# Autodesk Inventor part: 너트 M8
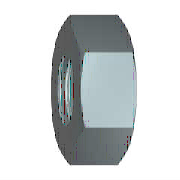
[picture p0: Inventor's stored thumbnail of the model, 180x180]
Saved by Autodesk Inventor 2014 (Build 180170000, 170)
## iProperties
IsCustomPart: 1
Created: 2012-02
Part Number: 너트 M8
Material: 강철, 연강
Description: 6각 너트 및 6각 가는 너트
Document SubType Name: Modeling
Standard: KS B 1012
Designer: mduedu
Standards Organization: KS
Language: ko-KR
Size Designation: M 8
Categories: <MemberInstance><Categories><Category DisplayName="조임쇠" InternalName="e4da775c-781d-43d5-af7c-5136215cf5a6" Mnemonic="FSTN"><Category DisplayName="너트" InternalN
Density: 1 g/cm^3
Appearance: 강철
Author: mduedu
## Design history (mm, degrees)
sketch "스케치1"
  geometry: L1 (-7.506, 0)-(-3.753, 6.5); L2 (-3.753, 6.5)-(3.753, 6.5); L3 (3.753, 6.5)-(7.506, 0); L4 (7.506, 0)-(3.753, -6.5); L5 (3.753, -6.5)-(-3.753, -6.5); L6 (-3.753, -6.5)-(-7.506, 0); 2 further points
  constraints: 12 end point, 1 coincident, 1 horizontal, 11 other
  dimensions: "d0" = 15.01111 distance of L3.end L1.start (= 1.1547 x SW)
extrude "본체" new body sketch "스케치1" distance "d1" = 5 (= KOH); taper "d2" = 0 deg
sketch "스케치2"
  geometry: L1 (0, 3.753)-(0, 7.506) reference; L2 (0, 7.506)-(5, 7.506) reference; L3 (5, 3.753)-(5, 7.506) reference; L4 (-1, 0)-(6, 0) reference; L5 (0.581, 7.506)-(0, 6.5); L6 (4.419, 7.506)-(5, 6.5)
  constraints: 4 end point, 4 point on line
  dimensions: "d3" = 30 deg angle of L1 L5 (= ANG1); "d4" = 30 deg angle of L3 L6 (= ANG2); "d5" = 13 diameter of L5.end L4 (= SW0); "d6" = 13 diameter of L6.end L4 (= SW01)
revolve "모따기1" sketch "스케치2" stored, may be unused: angle "d7" = 90 deg
sketch "스케치3"
  geometry: A1 r 6.5 centre (0, 0) between (-3.25, -5.629) and (3.25, -5.629) reference; 1 further point
  constraints: 1 coincident
hole "스레드" sketch "스케치3" at (0, 0) diameter "d25" = 6.647; stored, may be unused: countersink angle "d29" = 82 deg, drill point angle "d31" = 118 deg; dims "d26" = 6, "d27" = 4, "d28" = 2, "d30" = 8
workaxis "Work Axis1"
workplane "Work Plane1"
body "Solid1"
chamfer "모따기2" distance "d8" = 0.67658 (= -0.5 x GD1 + 0.5 x NND); stored, may be unused: angle "d9" = 30 deg, second distance "d40" = 0.67658 (= -0.5 x GD1 + 0.5 x NND)
chamfer "모따기3" distance "d10" = 0.67658 (= -0.5 x GD1 + 0.5 x NND); stored, may be unused: angle "d11" = 30 deg, second distance "d41" = 0.67658 (= -0.5 x GD1 + 0.5 x NND)
other parameters: "ANG1" = 30 deg [user parameter; used in 1 equation term], "ANG2" = 30 deg [user parameter; used in 1 equation term], "NND" = 8 [user parameter; used in 4 equation terms], "KOH" = 5 [user parameter; used in 1 equation term], "SW" = 13 [user parameter; used in 4 equation terms], "SW0" = 13 (= SW) [user parameter; used in 1 equation term], "SW01" = 13 (= SW) [user parameter; used in 1 equation term], "GD1" = 6.64684 (computed from THREADDIA, PTC, TOA) [user parameter; used in 4 equation terms], "d13" = 0, "d14" = 0, "d39" = 0, "d42" = 0, "GUL" = 0.67658 (= 0.541266 x PTC) [user parameter], "TPU" = 8 (computed from PTC) [user parameter], "THREADDIA" = 8 [user parameter; used in 1 equation term], "TOA" = 30 deg [user parameter; used in 1 equation term], "PTC" = 1.25 [user parameter; used in 4 equation terms], "E0" = 15.015 (= 1.155 x SW) [user parameter], "GAL" = 0.67658 (= 0.541266 x PTC) [user parameter]
